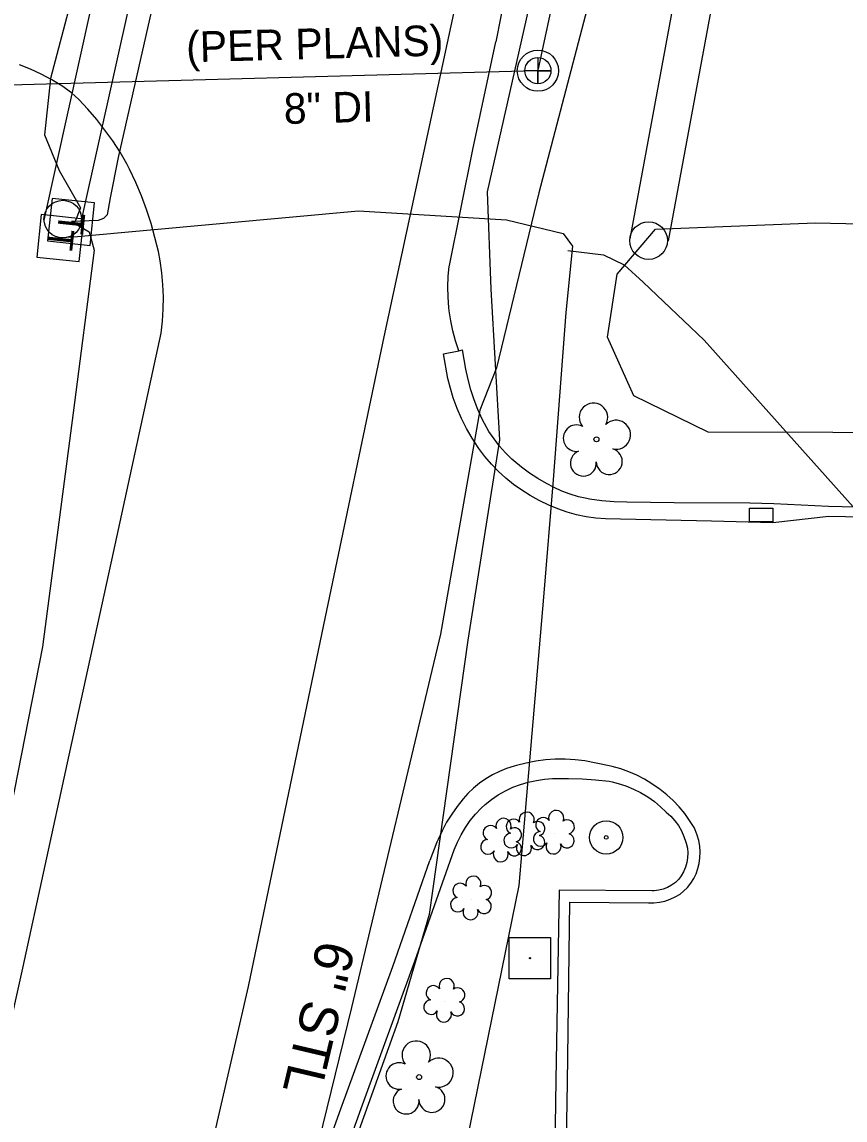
# Model space of a CAD drawing. Extents: x 1614427 to 1617186, y 896524 to 905462.
# Drawn here: x 1616144.4 to 1616251.9, y 899493 to 899636.5 of the extents above; entities that cross this region are included whole.
import ezdxf

# ---------------------------------------------------------------- set-up
doc = ezdxf.new("R2010")
doc.units = 0
for name, color, linetype in [('Exist Other Culture Sign Post CELL', 7, 'Continuous'), ('Exist Roads Curbs', 7, 'Continuous'), ('Exist Roads EOP', 7, 'Continuous'), ('Exist Roads EOP Other', 7, 'Continuous'), ('Exist Structure Minor Catch Basin', 7, 'Continuous'), ('Exist Utilities Gas UG Line SUE LOS B', 7, 'Continuous'), ('Exist Utilities Gas UG Line SUE LOS B Text', 7, 'Continuous'), ('Exist Utilities Other Pole CELL', 7, 'Continuous'), ('Exist Utilities Other Pole With Base CELL', 7, 'Continuous'), ('Exist Utilities Power UG Cable SUE LOS D', 7, 'Continuous'), ('Exist Utilities Sanitary Sewer Manhole CELL', 7, 'Continuous'), ('Exist Utilities Sanitary Sewer UG Line', 7, 'Continuous'), ('Exist Utilities Sanitary Sewer UG Line Text', 7, 'Continuous'), ('Exist Utilities Telephone Pedestal CELL', 7, 'Continuous'), ('Exist Utilities Telephone UG Cable SUE LOS B', 7, 'Continuous'), ('Exist Utilities Telephone UG Cable SUE LOS C', 7, 'Continuous'), ('Exist Utilities Telephone UG FO SUE LOS B', 7, 'Continuous'), ('Exist Utilities Telephone UG FO SUE LOS D', 7, 'Continuous'), ('Exist Utilities TV UG Cable SUE LOS D', 7, 'Continuous'), ('Exist Utilities TV UG FO Cable SUE LOS D', 7, 'Continuous'), ('Exist Utilities Water UG Line SUE LOS B', 7, 'Continuous'), ('Exist Vegetation Hedge Row', 7, 'Continuous'), ('Exist Vegetation Shrub CELL', 7, 'Continuous'), ('Exist Vegetation Tree CELL', 7, 'Continuous')]:
    doc.layers.add(name, color=color, linetype=linetype)

msp = doc.modelspace()

# ---------------------------------------------------------------- linework, layer by layer
at = {"layer": 'Exist Other Culture Sign Post CELL'}
for radius in [2.18, 0.24]:
    msp.add_circle((1616220.73, 899529.95), radius, dxfattribs=at)
at = {"layer": 'Exist Roads Curbs'}
for points in [[(1616239.46, 899573.59), (1616229.58, 899573.65), (1616223.4, 899573.75), (1616221.78, 899573.8), (1616220.16, 899573.93), (1616218.56, 899574.14), (1616218.2, 899574.2), (1616217.1, 899574.45), (1616216.01, 899574.78), (1616214.94, 899575.18), (1616213.91, 899575.65), (1616212.94, 899576.19), (1616211.8, 899576.83), (1616210.71, 899577.53), (1616209.66, 899578.3), (1616208.65, 899579.13), (1616208.4, 899579.35), (1616207.56, 899580.18), (1616206.78, 899581.07), (1616206.07, 899582.01), (1616205.41, 899582.99), (1616204.83, 899584.02), (1616204.54, 899584.59), (1616203.96, 899585.84), (1616203.46, 899587.12), (1616203.03, 899588.42), (1616202.68, 899589.75), (1616202.4, 899591.1), (1616201.94, 899593.62)], [(1616357.28, 899575.79), (1616352.98, 899573.86), (1616351.25, 899573.15), (1616349.49, 899572.51), (1616347.72, 899571.94), (1616345.92, 899571.45), (1616344.06, 899571.1), (1616342.4, 899570.98), (1616325.78, 899571.44), (1616311.19, 899571.72), (1616293.32, 899572.05), (1616274.06, 899572.63), (1616258.59, 899572.97), (1616249.75, 899573.16), (1616242.6, 899573.53), (1616239.46, 899573.59)], [(1616181.44, 899474.29), (1616188.71, 899494.53), (1616195.73, 899513.79), (1616200.86, 899528.31), (1616201.28, 899529.32), (1616201.77, 899530.3), (1616202.33, 899531.24), (1616202.96, 899532.14), (1616203.65, 899532.99), (1616204.4, 899533.78), (1616204.9, 899534.25), (1616205.75, 899534.91), (1616206.63, 899535.5), (1616207.57, 899536.03), (1616208.53, 899536.49), (1616209.53, 899536.87), (1616210.55, 899537.17), (1616211.6, 899537.4), (1616212.65, 899537.56), (1616213.72, 899537.63), (1616214.02, 899537.63), (1616215.79, 899537.66), (1616217.57, 899537.61), (1616219.34, 899537.48), (1616221.11, 899537.28), (1616221.5, 899537.2), (1616222.27, 899537.01), (1616223.29, 899536.68), (1616224.27, 899536.27), (1616225.22, 899535.8), (1616226.14, 899535.25), (1616227.01, 899534.64), (1616227.83, 899533.96), (1616228.56, 899533.26), (1616229.15, 899532.72), (1616229.68, 899532.13), (1616230.15, 899531.49), (1616230.55, 899530.8), (1616230.88, 899530.08), (1616231.14, 899529.33), (1616231.18, 899529.18), (1616231.32, 899528.55), (1616231.38, 899527.92), (1616231.36, 899527.28), (1616231.26, 899526.65), (1616231.08, 899526.04), (1616230.83, 899525.45), (1616230.5, 899524.91), (1616230.19, 899524.49), (1616229.75, 899524.07), (1616229.27, 899523.71), (1616228.73, 899523.41), (1616228.17, 899523.19), (1616227.58, 899523.04), (1616226.97, 899522.97), (1616226.72, 899522.97), (1616214.58, 899523.04), (1616214.15, 899498.27), (1616213.81, 899474.57)]]:
    msp.add_lwpolyline(points, dxfattribs=at)
at = {"layer": 'Exist Roads EOP'}
for points in [[(1616210.24, 899653.77), (1616206.3, 899633.88)], [(1616201.47, 899593.52), (1616201.05, 899594.8), (1616200.71, 899596.1), (1616200.43, 899597.42), (1616200.22, 899598.75), (1616200.17, 899599.17), (1616200.07, 899600.51), (1616200.04, 899601.86), (1616200.09, 899603.21), (1616200.22, 899604.56), (1616200.24, 899604.65), (1616203.32, 899619.79), (1616206.3, 899633.88)], [(1616140.14, 899493.23), (1616144.54, 899512.87), (1616150.36, 899539.69), (1616156.37, 899567.17), (1616162.59, 899595.81), (1616162.77, 899597.38), (1616162.87, 899598.96), (1616162.88, 899600.54), (1616162.82, 899602.12), (1616162.68, 899603.7), (1616162.45, 899605.27), (1616162.23, 899606.48), (1616161.79, 899608.33), (1616161.27, 899610.16), (1616160.68, 899611.97), (1616160.01, 899613.75), (1616159.27, 899615.51), (1616158.46, 899617.23), (1616158.1, 899617.94), (1616157.22, 899619.45), (1616156.27, 899620.92), (1616155.26, 899622.35), (1616154.18, 899623.73), (1616153.04, 899625.06), (1616151.84, 899626.33), (1616150.87, 899627.21), (1616149.63, 899628.11), (1616148.3, 899628.91), (1616146.93, 899629.63), (1616145.53, 899630.29), (1616144.09, 899630.88)], [(1616200.02, 899589.9), (1616199.47, 899593.13), (1616201.47, 899593.52), (1616201.94, 899593.62)], [(1616178.69, 899473.94), (1616186.08, 899494.49), (1616192.86, 899513.07), (1616197.69, 899526.92)]]:
    msp.add_lwpolyline(points, dxfattribs=at)
at = {"layer": 'Exist Roads EOP Other'}
for points in [[(1616258.56, 899571.68), (1616249.81, 899571.87), (1616242.49, 899571.03), (1616234.49, 899571.24), (1616220.65, 899571.54), (1616219.37, 899571.65), (1616218.1, 899571.83), (1616216.85, 899572.09), (1616215.61, 899572.43), (1616214.4, 899572.85), (1616213.21, 899573.34), (1616212.06, 899573.9), (1616211.95, 899573.96), (1616210.8, 899574.59), (1616209.69, 899575.29), (1616208.62, 899576.06), (1616207.6, 899576.88), (1616206.63, 899577.77), (1616205.72, 899578.72), (1616204.87, 899579.72), (1616204.08, 899580.77), (1616203.99, 899580.89), (1616203.2, 899582.11), (1616202.48, 899583.37), (1616201.83, 899584.66), (1616201.25, 899585.99), (1616200.75, 899587.35), (1616200.32, 899588.74), (1616200.02, 899589.9)], [(1616215.36, 899479.92), (1616215.66, 899497.93), (1616215.98, 899521.48), (1616226.23, 899521.39), (1616226.95, 899521.39), (1616227.68, 899521.47), (1616228.39, 899521.63), (1616229.08, 899521.86), (1616229.74, 899522.17), (1616230.36, 899522.55), (1616230.83, 899522.91), (1616231.34, 899523.41), (1616231.78, 899523.97), (1616232.15, 899524.57), (1616232.46, 899525.21), (1616232.7, 899525.88), (1616232.85, 899526.56), (1616232.96, 899527.3), (1616233, 899528.05), (1616232.95, 899528.79), (1616232.82, 899529.53), (1616232.62, 899530.25), (1616232.34, 899530.94), (1616232.21, 899531.22), (1616231.62, 899532.17), (1616230.97, 899533.08), (1616230.25, 899533.95), (1616229.47, 899534.76), (1616228.64, 899535.51), (1616227.76, 899536.2), (1616227.62, 899536.3), (1616226.7, 899536.96), (1616225.73, 899537.55), (1616224.72, 899538.08), (1616223.68, 899538.53), (1616222.61, 899538.9), (1616221.52, 899539.2), (1616221.11, 899539.29), (1616217.93, 899539.95), (1616216.65, 899540.1), (1616215.36, 899540.17), (1616214.07, 899540.17), (1616212.79, 899540.08), (1616211.51, 899539.91), (1616210.25, 899539.66), (1616209, 899539.34), (1616208.69, 899539.25), (1616207.72, 899538.95), (1616206.78, 899538.57), (1616205.87, 899538.13), (1616205, 899537.61), (1616204.18, 899537.02), (1616203.4, 899536.37), (1616202.67, 899535.67), (1616202.06, 899534.97), (1616201.27, 899534), (1616200.54, 899532.98), (1616199.88, 899531.92), (1616199.28, 899530.82), (1616198.76, 899529.68), (1616198.62, 899529.33), (1616197.69, 899526.92)]]:
    msp.add_lwpolyline(points, dxfattribs=at)
at = {"layer": 'Exist Structure Minor Catch Basin'}
msp.add_lwpolyline([(1616239.45, 899572.95), (1616242.47, 899572.94), (1616242.47, 899571.15), (1616239.44, 899571.16)], close=True, dxfattribs=at)
at = {"layer": 'Exist Utilities Gas UG Line SUE LOS B'}
msp.add_lwpolyline([(1616223.1, 899656.86), (1616211.93, 899614.15), (1616206.41, 899591.28), (1616204.23, 899585.74), (1616199.06, 899556.48), (1616187.46, 899507.75), (1616179.95, 899477.17), (1616174.33, 899453.44), (1616172.28, 899438.3), (1616170.68, 899423.65), (1616174.99, 899410.03), (1616190.2, 899390.02), (1616202.16, 899389.81), (1616231.06, 899387.63), (1616247.84, 899387.2), (1616260.52, 899387.43), (1616264.29, 899386.89), (1616281.13, 899384.3), (1616319.56, 899382.76), (1616367.63, 899381.53), (1616426.12, 899380.09), (1616473.53, 899378.89), (1616513.61, 899378.26), (1616557.59, 899378.05)], dxfattribs=at)
at = {"layer": 'Exist Utilities Other Pole CELL'}
for centre in [(1616149.75, 899610.71), (1616226.26, 899607.9)]:
    msp.add_circle(centre, 2.46, dxfattribs=at)
at = {"layer": 'Exist Utilities Other Pole With Base CELL'}
msp.add_line((1616210.77, 899514.17), (1616210.77, 899514.17), dxfattribs=at)
msp.add_lwpolyline([(1616208.05, 899516.87), (1616213.45, 899516.87), (1616213.45, 899511.47), (1616208.05, 899511.47), (1616208.05, 899516.87)], dxfattribs=at)
msp.add_circle((1616210.77, 899514.17), 0.0707, dxfattribs=at)
at = {"layer": 'Exist Utilities Power UG Cable SUE LOS D'}
msp.add_lwpolyline([(1616223.84, 899608.14), (1616243.67, 899715.3), (1616271.05, 899862.72), (1616287.19, 899947.04), (1616314.39, 900071.71)], dxfattribs=at)
at = {"layer": 'Exist Utilities Sanitary Sewer Manhole CELL'}
msp.add_lwpolyline([(1616211.8, 899631.82), (1616211.8, 899628.39), (1616211.8, 899630.1), (1616213.51, 899630.1), (1616210.08, 899630.1)], dxfattribs=at)
for radius in [2.69, 1.71]:
    msp.add_circle((1616211.8, 899630.1), radius, dxfattribs=at)
at = {"layer": 'Exist Utilities Sanitary Sewer UG Line'}
for p, q in [((1616249.82, 899808.06), (1616211.84, 899630.34)), ((1616211.55, 899630.1), (1615898.34, 899621.47))]:
    msp.add_line(p, q, dxfattribs=at)
at = {"layer": 'Exist Utilities Telephone Pedestal CELL'}
for p, q in [((1616150.87, 899610.42), (1616150.87, 899610.42)), ((1616149.45, 899608.3), (1616149.45, 899608.3))]:
    msp.add_line(p, q, dxfattribs=at)
for points in [[(1616148.35, 899613.42), (1616147.76, 899607.86), (1616153.32, 899607.27), (1616153.91, 899612.83), (1616148.35, 899613.42)], [(1616146.93, 899611.31), (1616146.34, 899605.75), (1616151.9, 899605.16), (1616152.49, 899610.72), (1616146.93, 899611.31)]]:
    msp.add_lwpolyline(points, dxfattribs=at)
at = {"layer": 'Exist Utilities Telephone UG Cable SUE LOS B'}
for points in [[(1616210.82, 899880.03), (1616214.88, 899878.3), (1616223.94, 899876.33), (1616225.37, 899875.48), (1616225.21, 899873.06), (1616219.37, 899841.05), (1616209.68, 899798.84), (1616199.04, 899757.59), (1616187.79, 899709.57), (1616181.23, 899693.06), (1616175.84, 899683.39), (1616170.4, 899676.62), (1616159.6, 899672.57), (1616158.07, 899672.03), (1616157.64, 899670.01), (1616156.25, 899659.82), (1616148.14, 899629.06), (1616147.35, 899621.71), (1616149.27, 899617.08), (1616152.04, 899612.2), (1616151.31, 899610.32), (1616150.87, 899610.42)], [(1616150.87, 899610.42), (1616153.18, 899609.07), (1616153.86, 899606.67), (1616151.11, 899585.39), (1616147.11, 899554.84), (1616140.6, 899521.99), (1616131.48, 899478.87), (1616125.05, 899448.4), (1616113.78, 899415.32), (1616111.46, 899406.05), (1616109.56, 899394.84), (1616108.47, 899383.92), (1616097.39, 899349.23), (1616084.09, 899315.91), (1616075.73, 899293.12), (1616071.62, 899290.61), (1616067.68, 899290.46)]]:
    msp.add_lwpolyline(points, dxfattribs=at)
at = {"layer": 'Exist Utilities Telephone UG Cable SUE LOS C'}
for points in [[(1616210.82, 899880.03), (1616215.09, 899877.1), (1616214.79, 899872.35), (1616208.69, 899842.15), (1616200.55, 899801.86), (1616192.43, 899768.48), (1616183.82, 899729.81), (1616177.9, 899703.99), (1616170.89, 899672.88), (1616161.53, 899638.94), (1616157, 899618.76), (1616155.95, 899613.5), (1616155.56, 899611.27), (1616155.08, 899610.81), (1616154.37, 899610.53), (1616150.87, 899610.42)], [(1616215.71, 899606.61), (1616220.38, 899606.04), (1616223.08, 899604.73), (1616225.54, 899602.46), (1616233.5, 899594.89), (1616256.27, 899569.42), (1616269, 899554.87), (1616277.71, 899545.89), (1616281.01, 899542.71), (1616287.61, 899542.52)]]:
    msp.add_lwpolyline(points, dxfattribs=at)
at = {"layer": 'Exist Utilities Telephone UG FO SUE LOS B'}
for points in [[(1616214.77, 899656.74), (1616205.17, 899614.27), (1616205.67, 899601.57), (1616206.78, 899581.86), (1616202.66, 899555.72), (1616197.61, 899519.87), (1616193.52, 899505.85), (1616183.34, 899477.46), (1616174.27, 899447.99), (1616168.42, 899428.4), (1616169.6, 899416.51), (1616176.34, 899400.32), (1616186.35, 899390.81), (1616200.22, 899386.46), (1616230.73, 899384.85)], [(1616149.45, 899608.3), (1616151.65, 899608.46), (1616188.38, 899611.81), (1616207.68, 899610.63), (1616215.12, 899608.85), (1616216.33, 899607.19), (1616215.47, 899598.51), (1616213.78, 899576.64), (1616212.53, 899561.31), (1616209.31, 899523.67), (1616199.92, 899477.56), (1616190.94, 899426.64), (1616189.51, 899413.84), (1616189.33, 899401.85), (1616189.9, 899399.55), (1616191.66, 899398.1), (1616198.1, 899397.89), (1616231.65, 899396.09), (1616264.93, 899394.59), (1616304.98, 899394.75), (1616347.91, 899394.68), (1616386.98, 899394.33)]]:
    msp.add_lwpolyline(points, dxfattribs=at)
at = {"layer": 'Exist Utilities Telephone UG FO SUE LOS D'}
msp.add_lwpolyline([(1616147.32, 899610.59), (1616176.63, 899742.88), (1616219.92, 899937.4), (1616266.21, 900145.35)], dxfattribs=at)
at = {"layer": 'Exist Utilities TV UG Cable SUE LOS D'}
msp.add_lwpolyline([(1616228.85, 899607.89), (1616275.98, 899862.3), (1616292.03, 899946), (1616319.37, 900070.73), (1616351.28, 900220.72)], dxfattribs=at)
at = {"layer": 'Exist Utilities TV UG FO Cable SUE LOS D'}
msp.add_lwpolyline([(1616152.19, 899610.51), (1616181.4, 899742.23), (1616224.51, 899936.62), (1616270.68, 900144.79), (1616313.06, 900339.79), (1616354.51, 900530.51), (1616387.28, 900682.32), (1616420.05, 900834.14), (1616462.24, 901026.32), (1616489.27, 901166.41), (1616544.61, 901400.99), (1616575.34, 901543.24), (1616671.95, 901701.27)], dxfattribs=at)
at = {"layer": 'Exist Utilities Water UG Line SUE LOS B'}
msp.add_lwpolyline([(1616205.16, 899658.03), (1616191.69, 899595.33), (1616183.79, 899557.72), (1616173.96, 899510.49), (1616162.12, 899458.99), (1616153.34, 899426.63), (1616143.66, 899387.67), (1616129.79, 899345.08), (1616113.12, 899294), (1616097.38, 899250.2), (1616076.09, 899202.34), (1616057.7, 899163.22), (1616049.64, 899146.8), (1616026.97, 899101.57)], dxfattribs=at)
at = {"layer": 'Exist Vegetation Hedge Row'}
msp.add_lwpolyline([(1616363.03, 899583.15), (1616348.55, 899579.11), (1616331.06, 899579.6), (1616319.44, 899577.29), (1616309.24, 899578.42), (1616297.42, 899586.35), (1616291, 899585.92), (1616282.85, 899582.74), (1616234.04, 899582.88), (1616224.35, 899587.63), (1616220.9, 899595.27), (1616222.16, 899603.5), (1616227.14, 899609.41), (1616248.04, 899610.23), (1616311.22, 899608.84), (1616344.33, 899601.81), (1616354.93, 899599.71)], dxfattribs=at)
at = {"layer": 'Exist Vegetation Shrub CELL'}
for p, q in [((1616210.11, 899530.23), (1616210.11, 899530.23)), ((1616213.97, 899530.45), (1616213.97, 899530.45)), ((1616207.08, 899529.41), (1616207.08, 899529.41)), ((1616203.14, 899521.87), (1616203.14, 899521.87)), ((1616199.65, 899508.49), (1616199.65, 899508.49))]:
    msp.add_line(p, q, dxfattribs=at)
for centre, radius, start, end in [((1616210.34, 899532.27), 0.99, 334.8391, 200.4717), ((1616212.48, 899531.58), 0.968, 35.8908, 245.4216), ((1616214.19, 899532.49), 0.99, 334.8391, 200.4717), ((1616205.6, 899530.54), 0.968, 35.8908, 245.4216), ((1616207.31, 899531.45), 0.99, 334.8391, 200.4717), ((1616208.63, 899531.36), 0.968, 35.8908, 245.4216), ((1616208.75, 899530.28), 0.929, 284.4567, 126.0861), ((1616211.78, 899531.1), 0.929, 284.4567, 126.0861), ((1616215.64, 899531.32), 0.929, 284.4567, 126.0861), ((1616205.28, 899528.71), 0.955, 95.1099, 327.9534), ((1616208.31, 899529.53), 0.955, 95.1099, 327.9534), ((1616211.75, 899529.3), 0.937, 204.9913, 73.4601), ((1616212.17, 899529.75), 0.955, 95.1099, 327.9534), ((1616215.6, 899529.52), 0.937, 204.9913, 73.4601), ((1616208.72, 899528.48), 0.937, 204.9913, 73.4601), ((1616209.98, 899528.55), 0.984, 151.2797, 21.387), ((1616213.84, 899528.77), 0.984, 151.2797, 21.387), ((1616206.95, 899527.73), 0.984, 151.2797, 21.387), ((1616201.66, 899522.99), 0.968, 35.8908, 245.4216), ((1616203.37, 899523.91), 0.99, 334.8391, 200.4717), ((1616204.81, 899522.73), 0.929, 284.4567, 126.0861), ((1616201.34, 899521.16), 0.955, 95.1099, 327.9534), ((1616204.78, 899520.94), 0.937, 204.9913, 73.4601), ((1616203.01, 899520.18), 0.984, 151.2797, 21.387), ((1616199.88, 899510.53), 0.99, 334.8391, 200.4717), ((1616198.17, 899509.62), 0.968, 35.8908, 245.4216), ((1616201.32, 899509.36), 0.929, 284.4567, 126.0861), ((1616197.85, 899507.78), 0.955, 95.1099, 327.9534), ((1616201.29, 899507.56), 0.937, 204.9913, 73.4601), ((1616199.52, 899506.81), 0.984, 151.2797, 21.387)]:
    msp.add_arc(centre, radius, start, end, dxfattribs=at)
at = {"layer": 'Exist Vegetation Tree CELL'}
for p, q in [((1616219.45, 899581.95), (1616219.45, 899581.95)), ((1616196.29, 899498.63), (1616196.29, 899498.63))]:
    msp.add_line(p, q, dxfattribs=at)
for centre in [(1616219.45, 899581.95), (1616196.29, 899498.63)]:
    msp.add_circle(centre, 0.326, dxfattribs=at)
for centre, radius, start, end in [((1616219.06, 899584.82), 1.86, 330.1651, 219.7134), ((1616222, 899582.54), 1.9, 257.1011, 134.1999), ((1616216.84, 899582.1), 1.73, 62.6636, 279.3457), ((1616217.74, 899578.83), 1.69, 111.5671, 6.231), ((1616221.12, 899579.05), 1.7, 181.2822, 74.56), ((1616195.91, 899501.5), 1.86, 330.1651, 219.7134), ((1616198.84, 899499.22), 1.9, 257.1011, 134.1999), ((1616193.69, 899498.78), 1.73, 62.6636, 279.3457), ((1616194.59, 899495.51), 1.69, 111.5671, 6.231), ((1616197.96, 899495.73), 1.7, 181.2822, 74.56)]:
    msp.add_arc(centre, radius, start, end, dxfattribs=at)

# ---------------------------------------------------------------- texts
at = {"layer": 'Exist Utilities Gas UG Line SUE LOS B Text'}
msp.add_text('6" STL', height=5, rotation=256.7289, dxfattribs=at).set_placement((1616183.1, 899516.7))
at = {"layer": 'Exist Utilities Sanitary Sewer UG Line Text'}
for s, p in [('(PER PLANS)', (1616165.91, 899631.19)), ('8" DI', (1616178.66, 899623.13))]:
    msp.add_text(s, height=4, rotation=1.5264, dxfattribs=at).set_placement(p)
at = {"layer": 'Exist Utilities Telephone Pedestal CELL'}
for p in [(1616149.29, 899611.72), (1616147.87, 899609.61)]:
    msp.add_text('T', height=3.42, rotation=263.9492, dxfattribs=at).set_placement(p)

doc.saveas('drawing.dxf')
